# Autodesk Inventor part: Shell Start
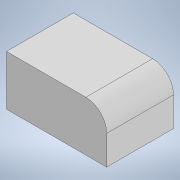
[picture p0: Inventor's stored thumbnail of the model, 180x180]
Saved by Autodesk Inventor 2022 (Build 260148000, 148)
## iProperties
Created: 2019-02
Part Number: Shell Start
Material: Generic
Document SubType Name: Modeling
Designer: John Helfen
Density: 1 g/cm^3
Appearance: Default
Author: John Helfen
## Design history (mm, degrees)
sketch "Sketch1"
  geometry: L1 (0, 0)-(38.1, 0); L2 (38.1, 0)-(38.1, 19.05); L3 (38.1, 19.05)-(0, 19.05); L4 (0, 19.05)-(0, 0)
  constraints: 8 end point, 2 parallel, 1 horizontal, 1 perpendicular
  dimensions: "d0" = 38.1 distance of L3.end L2.end; "d1" = 19.05 distance of L2.end L1.end
extrude "Extrusion1" new body sketch "Sketch1" distance "d2" = 25.4; taper "d3" = 0 deg
fillet "Fillet1" dims "d4" = 7.9375
body "Solid1"
